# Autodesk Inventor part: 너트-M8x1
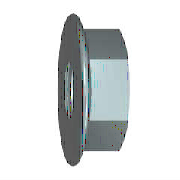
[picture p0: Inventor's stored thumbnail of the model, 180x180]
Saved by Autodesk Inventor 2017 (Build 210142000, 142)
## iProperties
Created: 2015-12
Part Number: 너트-M8x1
Material: 스테인리스강
Description: 플랜지붙이 6각 너트 - 일반 스레드
Document SubType Name: Modeling
Standard: ISO 4161
Designer: mdu
Standard Revision: 2판 1999-03-15
Standards Organization: ISO
Language: ko-KR
Size Designation: M8
Categories: <MemberInstance><Categories><Category DisplayName="조임쇠" InternalName="e4da775c-781d-43d5-af7c-5136215cf5a6" Mnemonic="FSTN"><Category DisplayName="너트" InternalN
Density: 8.08 g/cm^3
Appearance: 강철
Mass: 9.03298 g
Surface Area: 8.90186 cm^2
Volume: 1.11794 cm^3
Author: mdu
IsCustomPart: 1
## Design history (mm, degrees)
sketch "스케치1"
  geometry: L1 (-1.844, 0)-(9.641, 0) reference; L2 (3.107, 6.5)-(2.288, 8.257); L3 (3.107, 6.5)-(8, 6.5); L4 (8, 6.5)-(8, 0); L5 (3.107, 6.5)-(3.107, 0); L6 (0, -1.835)-(0, 11.01) reference; A1 r 1.2 centre (1.2, 7.75) between (2.288, 8.257) and (0, 7.75); 1 further point
  constraints: 8 end point, 3 point on line, 2 perpendicular, 2 point on circle, 2 tangent, 1 centre point, 1 parallel
  dimensions: "d2" = 13 diameter of L3 L1 (= SW); "d4" = 17.9 dimension on A1 L1 (= LADI); "d5" = 1.2 radius of A1 (= PHH); "d15" = 8 distance between parallel lines of L4 L6 (= KOH); "d16" = 25 deg angle of L6 L2 (= KEWI)
revolve "링" sketch "스케치1" stored, may be unused: angle "d8" = 90 deg
sketch "스케치2"
  geometry: L1 (-6.5, -3.753)-(-6.5, 3.753); L2 (-6.5, 3.753)-(0, 7.506); L3 (0, 7.506)-(6.5, 3.753); L4 (6.5, 3.753)-(6.5, -3.753); L5 (6.5, -3.753)-(0, -7.506); L6 (0, -7.506)-(-6.5, -3.753); C1 r 4.9 at (0, 0); C2 r 7.75 at (0, 0) reference; 1 further point
  constraints: 12 end point, 1 centre point, 1 coincident, 1 vertical, 11 other
  dimensions: "d6" = 15.01111 distance of L5.end L2.end (= 1.1547 x SW)
extrude "본체" join sketch "스케치2" distance "d7" = 8 (= KOH); taper "d9" = 0 deg
sketch "스케치3"
  geometry: L1 (2.638, 7.506)-(8, 7.506) reference; L2 (8, 3.753)-(8, 7.506) reference; L3 (0, -7.75)-(0, 7.75) reference; L4 (-1.6, 0)-(9.6, 0) reference; L5 (7.419, 7.506)-(8, 6.5)
  constraints: 2 end point, 2 point on line
  dimensions: "d10" = 30 deg angle of L2 L5 (= ANG1); "d11" = 13 diameter of L5.end L4 (= SW0)
revolve "모따기1" sketch "스케치3" stored, may be unused: angle "d24" = 90 deg
sketch "스케치4"
  geometry: C1 r 7.75 at (0, 0) reference; 1 further point
  constraints: 1 coincident
hole "스레드" sketch "스케치4" at (0, 0) diameter "d25" = 6.647; stored, may be unused: countersink angle "d29" = 82 deg, drill point angle "d31" = 118 deg; dims "d26" = 6, "d27" = 4, "d28" = 2, "d30" = 8
workaxis "Work Axis1"
workplane "Work Plane1"
body "Solid1"
chamfer "모따기2" distance "d12" = 0.67658 (= -0.5 x GD1 + 0.5 x NND); stored, may be unused: angle "d13" = 30 deg, second distance "d46" = 0.67658 (= -0.5 x GD1 + 0.5 x NND)
chamfer "모따기3" distance "d51" = 0.67658 (= -0.5 x GD1 + 0.5 x NND); stored, may be unused: second distance "d52" = 2, angle "d53" = 45 deg
other parameters: "ANG1" = 30 deg [user parameter; used in 1 equation term], "KEWI" = 25 deg [user parameter; used in 1 equation term], "NND" = 8 [user parameter; used in 4 equation terms], "LADI" = 17.9 [user parameter; used in 2 equation terms], "SW" = 13 [user parameter; used in 3 equation terms], "PHH" = 1.2 [user parameter; used in 3 equation terms], "KOH" = 8 (= NND) [user parameter; used in 2 equation terms], "SW0" = 13 [user parameter; used in 1 equation term], "GD1" = 6.64684 (computed from THREADDIA, PTC, TOA) [user parameter; used in 3 equation terms], "d1" = 17.9 (= LADI), "d3" = 1.2 (= PHH), "d45" = 0, "d47" = 0, "d49" = 0, "d54" = 0, "GUL" = 0.67658 (= 0.541266 x PTC) [user parameter], "TPU" = 8 (computed from PTC) [user parameter], "RR" = 1.2 (= PHH) [user parameter], "THREADDIA" = 8 [user parameter; used in 1 equation term], "TOA" = 30 deg [user parameter; used in 1 equation term], "PTC" = 1.25 [user parameter; used in 4 equation terms], "GAL" = 0.67658 (= 0.541266 x PTC) [user parameter], "E0" = 15.015 (= 1.155 x SW) [user parameter]
